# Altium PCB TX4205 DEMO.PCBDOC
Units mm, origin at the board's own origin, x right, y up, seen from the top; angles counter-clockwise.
Board outline 48.25 x 40.25 mm, 2 copper layers (Top Layer, Bottom Layer); 17 components, 8 nets, 42 pads, 163 vias.
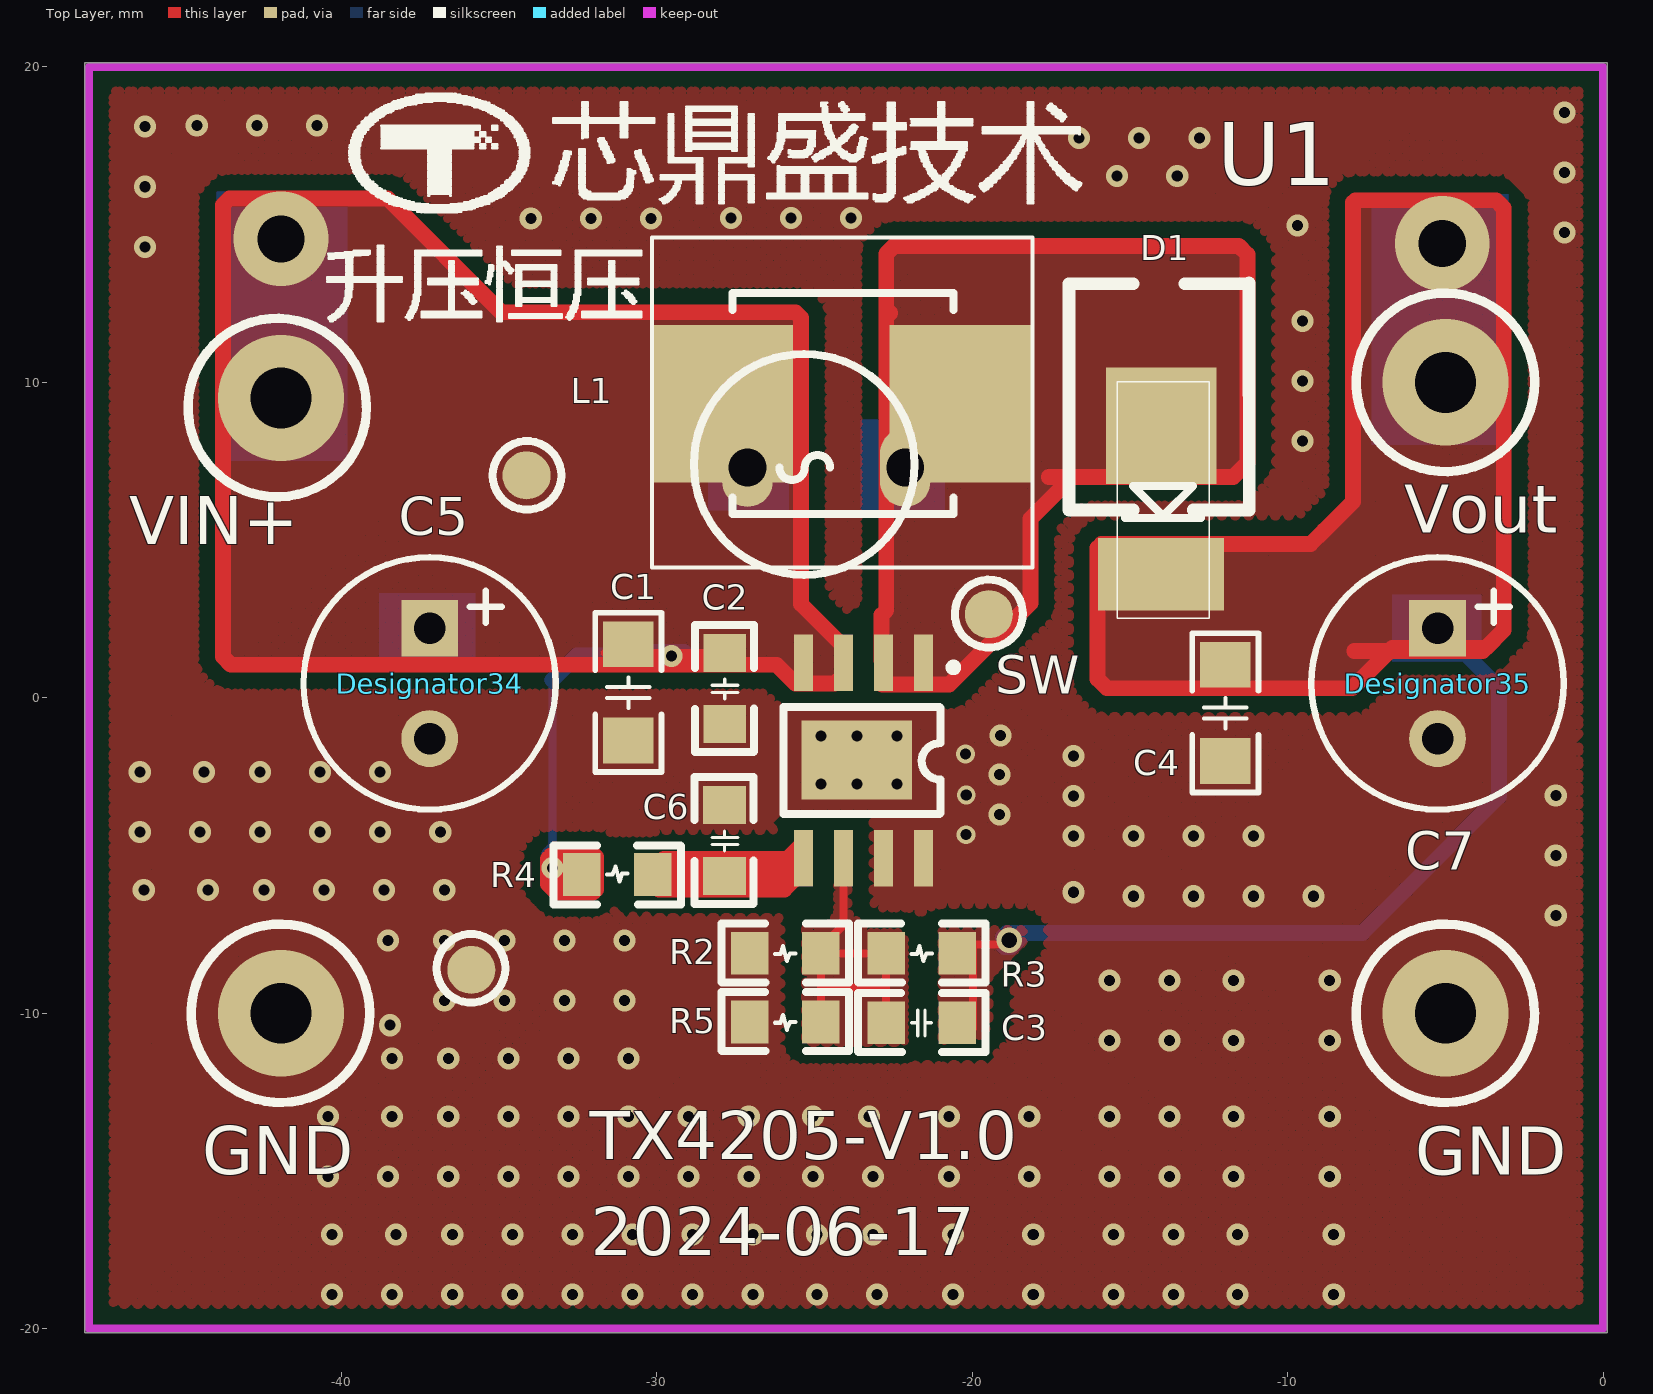
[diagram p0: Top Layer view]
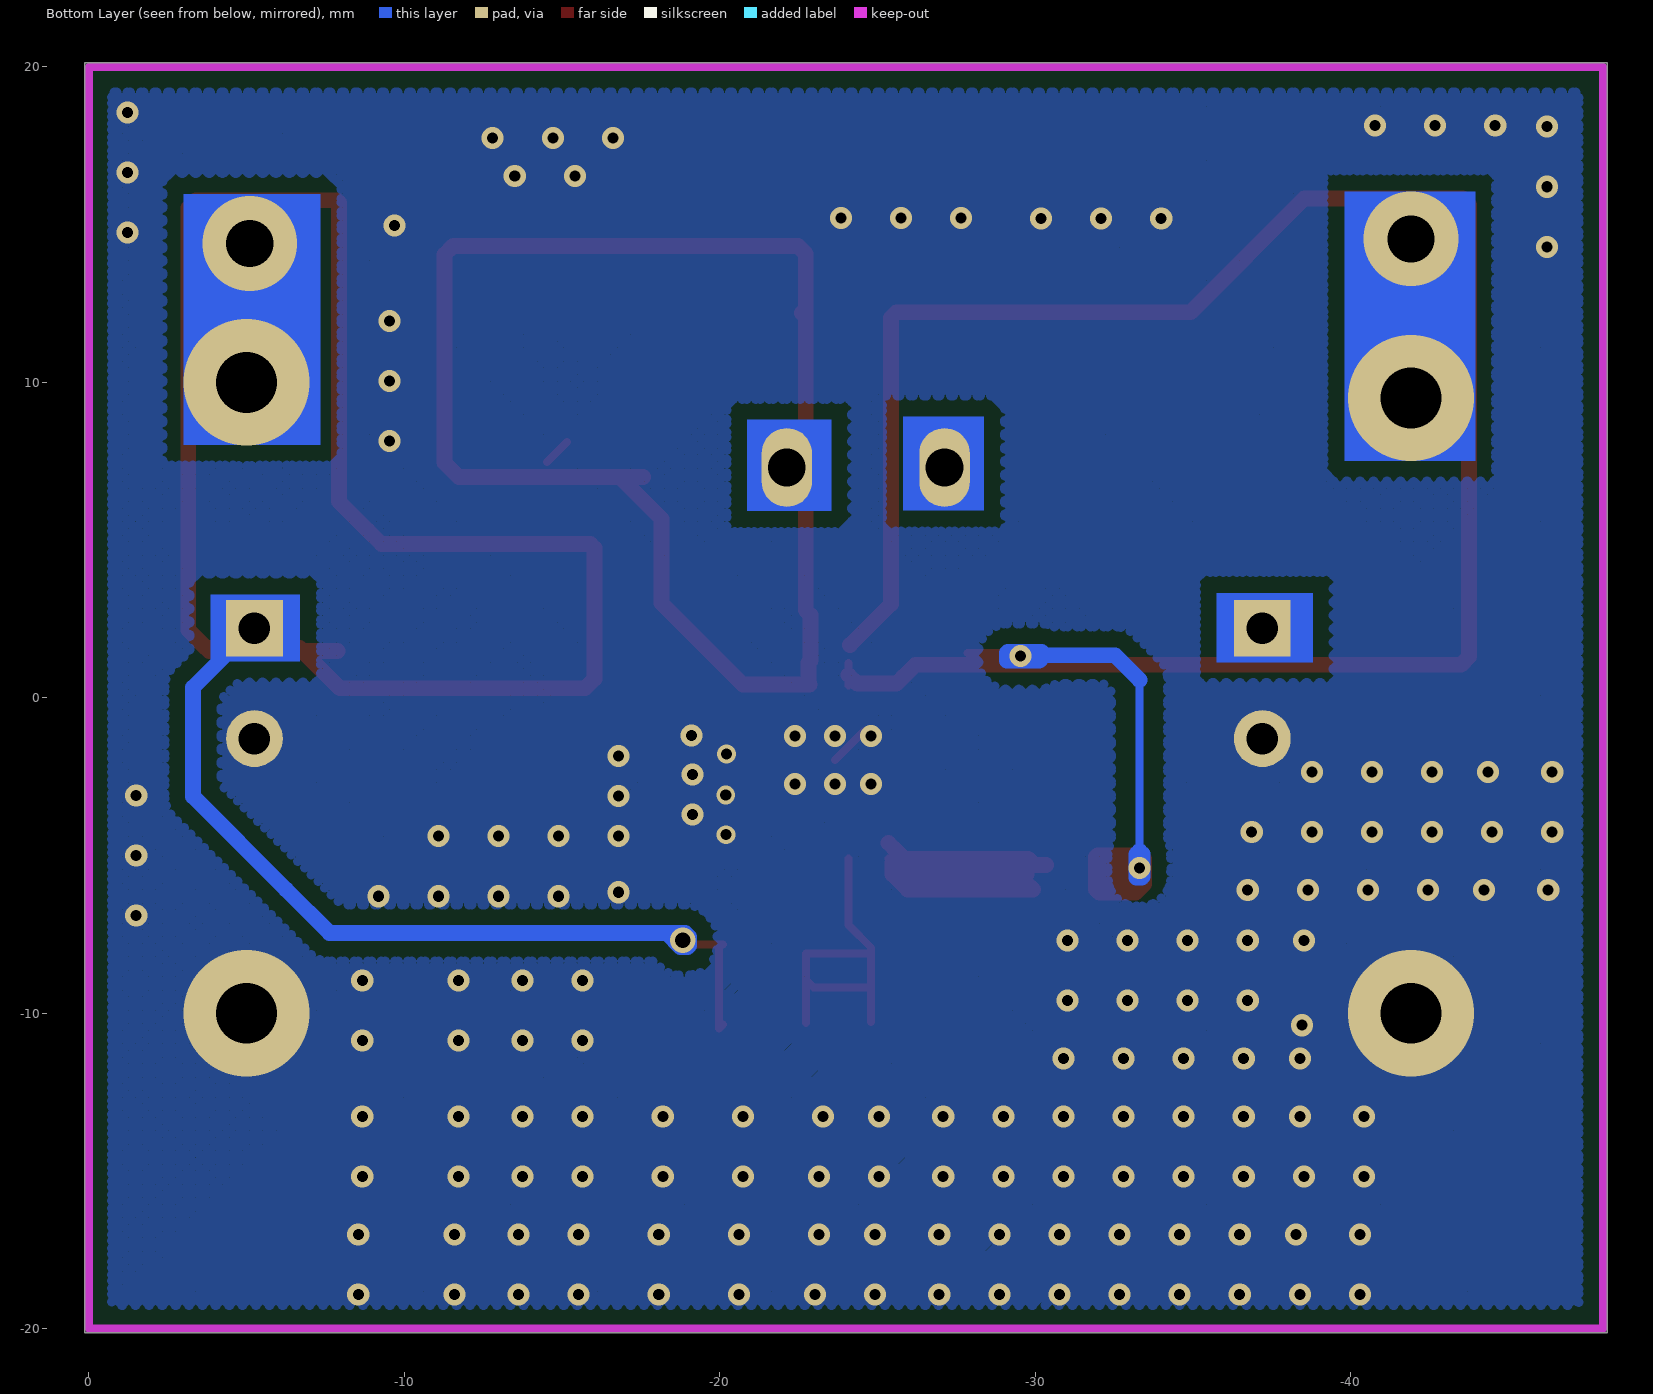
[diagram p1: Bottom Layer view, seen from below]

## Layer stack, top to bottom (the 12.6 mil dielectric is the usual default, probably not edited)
Top Layer: signal copper 0.0356
Dielectric: dielectric 0.32, FR-4, Dk 4.8
Bottom Layer: signal copper 0.0356

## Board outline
-48.127,-20.127 0.127,-20.127 0.127,20.127 -48.127,20.127

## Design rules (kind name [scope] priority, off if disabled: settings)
Clearance [All] p1: gap=0.5
PlaneConnect [All] p1: planeconnectstyle=Direct reliefexpansion=0.508 reliefentries=4 reliefconductorwidth=0.254 reliefairgap=0.254
PolygonConnect [All] p1: connectstyle=Direct reliefconductorwidth=0.254 reliefentries=4 polygonreliefangle="90 Angle"
RoutingLayers [All] p1: top layer_v5=FALSE bottom layer_v5=FALSE
RoutingVias [All] p1: holewidth=0.711 width=1.27 viastyle="Through Hole" minholewidth=0.711 minwidth=1.27 maxholewidth=0.711 maxwidth=1.27
SilkscreenOverComponentPads [All] p1: minsilkscreentomaskgap=0.254
SolderMaskExpansion [All] p1: expansion=0.102
TestPointUsage FabricationTestPointUsage [All] p1: valid=0 allowmultiple=FALSE
Testpoint FabricationTestpoint [All] p1: side=3 testpointundercomponent=TRUE minsize=1.016 maxsize=2.54 preferedsize=1.524 minholesize=0 maxholesize=1.016 preferedholesize=0.813 testpointgrid=0.025 style=297 order=0-112345678
Width [All] p1: maxlimit=1 minlimit=0.254 preferedwidth=0.5
21 further rules are at their usual default settings.

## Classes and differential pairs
component class XY9101A-B: C1 C2 C3 C4 C6 D1 L1 R2 R3 R4 U1

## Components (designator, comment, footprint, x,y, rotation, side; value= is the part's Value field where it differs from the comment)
C1 "Cap" C1206 -30.898,-1.353 r90 top
C2 "Cap" C0805 -27.844,-0.829 r90 top
C3 "Cap" C0805 -22.725,-10.3 r0 top
C4 "Cap" C1206 -11.973,-2.003 r90 top
C6 "Cap" C0805 -27.85,-5.65 r90 top
D1 "D Schottky" "Schottky Diode 20x10" -15.535,10.144 r270 top
Designator34 "Comment" C-RB-8 -37.35,-9.35 r270 top
Designator35 "Comment" C-RB-8 -5.4,-9.35 r270 top
L1 "Inductor" "inductor 10 x 10" -30.13,4.124 r0 top
R2 "Res1" R0805 -27.05,-8.1 r0 top
R3 "Res1" R0805 -22.725,-8.1 r0 top
R4 "Res1" R0805 -30.125,-5.6 r180 top
R5 "Res1" R0805 -27.05,-10.275 r0 top
U1 "TX4205" SOP8-Epad -26.193,2.092 r270 top
? "Comment" LOGO -36.875,17.775 r0 top
? "" LS7*7 -21.125,9.325 r0 top
? "" L2*3.5 -27.124,7.3 r0 top

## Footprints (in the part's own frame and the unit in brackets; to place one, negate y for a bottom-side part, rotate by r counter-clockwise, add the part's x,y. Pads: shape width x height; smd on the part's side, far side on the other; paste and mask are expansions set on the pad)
C0805 [mm]
  rect 1.2x1.35 smd: 1(0,0) 2(2.25,0)
  silkscreen extent -0.89,-0.93 3.14,0.95
C1206 [mm]
  rect 1.45x1.6 smd: 1(0,0) 2(3.05,0)
  silkscreen extent -1,-1.05 4.05,1.05
C-RB-8 [mm]
  rect 1.8x1.8 hole 1: 1(-11.557,0.152)
  round 1.8 hole 1: 2(-8.057,0.152)
  silkscreen extent -13.81,-3.85 -5.81,4.15
"inductor 10 x 10" [mm]
  rect 3x5 smd: 1(1.5,5.2) 2(10.5,5.2)
  silkscreen extent -0.03,0 12.04,10.46
L2*3.5 [mm]
  oval 1.6x2.5 hole 1.2: 1(0,0) 2(5,0)
  silkscreen extent -1.7,-3.4 5.3,3.6
LOGO [mm]
  silkscreen extent -2.88,-2.39 20.34,1.37
LS7*7 [mm]
  rect 3x5 smd: 1(0,0) 2(-6.05,0)
  silkscreen extent -6.48,-3.5 0.52,3.5
R0805 [mm]
  rect 1.2x1.35 smd: 1(0,0) 2(2.25,0)
  silkscreen extent -0.89,-0.93 3.14,0.95
"Schottky Diode 20x10" [mm]
  rect 3.7x3.5 smd: 1(1.524,1.524)
  rect 2.3x4 smd: 2(6.223,1.524)
  silkscreen extent 0.13,0.13 7.62,3.05
SOP8-Epad [mm]
  rect 1.8x0.6 smd: 1(0.981,4.653) 2(0.981,3.383) 3(0.981,2.113) 4(0.981,0.843) 5(7.181,0.843) 6(7.181,2.113) 7(7.181,3.383) 8(7.181,4.653)
  rect 2.5x3.5 smd: 1(4.064,2.54)
  silkscreen extent 1.01,0.21 5.78,5.72

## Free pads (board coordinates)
  round 1.524 smd: 1(-35.875,-8.625) 1(-34.125,7.05) 1(-19.47,2.651)

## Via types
v1: diameter 0.7, hole 0.35, Top Layer to Bottom Layer, 153 vias
v2: diameter 4, hole 1.93, Top Layer to Bottom Layer, 4 vias
v3: diameter 0.6, hole 0.35, Top Layer to Bottom Layer, 3 vias
v4: diameter 3, hole 1.5, Top Layer to Bottom Layer, 2 vias
v5: diameter 0.8, hole 0.5, Top Layer to Bottom Layer, 1 vias

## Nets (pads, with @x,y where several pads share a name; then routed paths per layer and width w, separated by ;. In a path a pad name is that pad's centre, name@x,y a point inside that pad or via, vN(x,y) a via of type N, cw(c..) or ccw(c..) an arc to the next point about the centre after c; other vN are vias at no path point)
COMP: 
COMPC: 
GND: C1.1 C2.1 C4.1 C6.2 Designator34.2 Designator35.2 pad.1@-35.875,-8.625 R2.1 R5.1 U1.1@-23.653,-1.972 U1.7 U1.8 | length 1.3
  Top Layer w0.254: U1.1@-24.574,-1.051 U1.1@-23.653,-1.972
  other v1: -40.29,-18.92 -38.385,-18.92 -36.48,-18.92 -34.575,-18.92 -32.67,-18.92 -30.765,-18.92 -28.86,-18.92 -26.955,-18.92 -24.923,-18.92 -23.018,-18.92 -20.605,-18.92 -18.065,-18.92 -15.525,-18.92 -13.62,-18.92 -11.588,-18.92 -8.54,-18.92 -40.29,-17.015 -38.258,-17.015 -36.48,-17.015 -34.575,-17.015 -32.67,-17.015 -30.765,-17.015 -28.86,-17.015 -26.955,-17.015 -24.923,-17.015 -23.145,-17.015 -20.605,-17.015 -18.065,-17.015 -15.525,-17.015 -13.62,-17.015 -11.588,-17.015 -8.54,-17.015 -40.417,-15.18 -38.512,-15.18 -36.607,-15.18 -34.702,-15.18 -32.797,-15.18 -30.892,-15.18 -28.987,-15.18 -27.082,-15.18 -25.05,-15.18 -23.145,-15.18 -20.732,-15.18 -18.192,-15.18 -15.652,-15.18 -13.747,-15.18 -11.715,-15.18 -8.667,-15.18 -40.417,-13.275 -38.385,-13.275 -36.607,-13.275 -34.702,-13.275 -32.797,-13.275 -30.892,-13.275 -28.987,-13.275 -27.082,-13.275 -25.05,-13.275 -23.272,-13.275 -20.732,-13.275 -18.192,-13.275 -15.652,-13.275 -13.747,-13.275 -11.715,-13.275 -8.667,-13.275 -38.385,-11.427 -36.607,-11.427 -34.702,-11.427 -32.797,-11.427 -30.892,-11.427 -15.652,-10.862 -13.747,-10.862 -11.715,-10.862 -8.667,-10.862 -38.448,-10.378 -36.734,-9.592 -34.829,-9.592 -32.924,-9.592 -31.019,-9.592 -15.652,-8.957 -13.747,-8.957 -11.715,-8.957 -8.667,-8.957 -38.512,-7.687 -36.734,-7.687 -34.829,-7.687 -32.924,-7.687 -31.019,-7.687 -14.89,-6.29 -12.985,-6.29 -11.08,-6.29 -9.175,-6.29 -16.795,-6.163 -46.259,-6.093 -44.227,-6.093 -42.449,-6.093 -40.544,-6.093 -38.639,-6.093 -36.734,-6.093 -16.795,-4.385 -14.89,-4.385 -12.985,-4.385 -11.08,-4.385 -46.386,-4.258 -44.481,-4.258 -42.576,-4.258 -40.671,-4.258 -38.766,-4.258 -36.861,-4.258 -19.14,-3.698 -16.795,-3.115 -24.796,-2.734 -23.653,-2.734 -22.383,-2.734 -19.139,-2.426 -46.386,-2.353 -44.354,-2.353 -42.576,-2.353 -40.671,-2.353 -38.766,-2.353 -16.795,-1.845 -24.796,-1.21 -23.653,-1.21 -22.383,-1.21 -19.104,-1.189 -9.693,14.973
  other v2: -41.908,-10 -5,-10
  other v3: -20.196,-4.34 -20.188,-3.075 -20.208,-1.782
NetC3_1: C3.1 R2.2 R3.1 R5.2 U1.6 | length 11.9
  Top Layer w0.254: R5.2 -24.8,-9.175 ; U1.6 -24.08,-7.205 -24.8,-7.925 R2.2 ; C3.1 -22.725,-8.925 ; -24.8,-9.175 R2.2 ; -24.8,-9.175 -22.975,-9.175 -22.725,-8.925 ; R2.2 R3.1 -22.725,-8.925
NetC3_2: C3.2 C4.2 D1.2 Designator35.1 R3.2 | length 90.9
  Top Layer w0.254: C3.2@-20.097,-10.354 -19.97,-10.481 R3.2@-19.97,-7.941 ; R3.2@-20.097,-7.814 -18.954,-7.814 v5(-18.827,-7.687)
  Top Layer w0.5: -7.89,1.485 -3.815,1.485 -3.675,1.625 ; -7.825,0.425 -7.175,1.075 -6.675,1.575 ; -6.675,1.575 -3.725,1.575 -3.15,2.15 -3.15,15.525 -3.25,15.625 -3.4,15.775 -3.9,15.775 -4.225,15.775 -7.85,15.775 -7.925,15.7 -7.925,6.225 -8.85,5.3 -9.275,4.875 -15.9,4.875 -16.025,4.75 -16.025,0.6 -15.725,0.3 -7.95,0.3 -6.675,1.575
  Bottom Layer w0.254: v5(-18.827,-7.687) v5@-18.597,-7.457
  Bottom Layer w0.5: v5(-18.827,-7.687) -18.597,-7.457 -7.632,-7.457 -6.25,-6.075 -3.3,-3.125 -3.3,0.325 Designator35.1@-5.45,2.475 ; -18.125,-7.457 -18.907,-7.457 -19.025,-7.575 -19.025,-7.85 -18.975,-7.9 -18.75,-7.9 -18.307,-7.457 -18.1,-7.457
  other v2: -5,10
  other v4: -5.1,14.4
NetC6_1: C6.1 R4.1 U1.5 | length 23.8
  Top Layer w0.254: R4.1@-29.908,-5.401 -27.85,-5.401 C6.1@-27.807,-5.401 ; C6.1@-27.742,-5.337 -25.598,-5.337 U1.5
  Top Layer w0.5: R4.1@-30.35,-5.3 -30.125,-5.3 -29.975,-5.3 -29.775,-5.1 -27.85,-5.1 -25.85,-5.1 -25.595,-4.845 U1.5@-25.35,-4.6 ; R4.1@-29.722,-5.597 -27.85,-5.597 U1.5@-25.472,-5.597 ; U1.5@-25.472,-5.211 U1.5@-25.472,-5.597 ; -25.875,-6 U1.5@-25.472,-5.597 ; -25.875,-6 -27.85,-6 -29.85,-6 -29.925,-6.075 -27.85,-6.075 -25.95,-6.075 -25.875,-6 ; -25.875,-6 U1.5@-25.472,-5.597
NetD1_1: ?.1@-21.125,9.325 ?.2@-22.124,7.3 D1.1 L1.2 pad.1@-19.47,2.651 U1.1@-21.54,1.111 U1.2 | length 49.9
  Top Layer w0.254: U1.2@-22.95,0.375 U1.2@-22.925,0.35 ; D1.1@-15.154,8.112 -14.837,7.794 D1.1@-14.519,7.477
  Top Layer w0.5: -22.6,12.2 -22.725,12.075 ; -17.575,7 -16.825,7 ; -22.725,12.075 -22.725,9.325 -22.725,7.3 -22.725,2.775 -22.875,2.625 -22.875,1.176 U1.2 -22.81,0.465 -22.85,0.425 -22.81,0.425 -21.54,0.425 -20.725,0.425 -18.985,2.165 -18.15,3 -18.15,5.675 -16.825,7 ; -22.725,12.075 -22.725,14.075 -22.475,14.325 -11.55,14.325 -11.275,14.05 -11.275,7.45 -11.725,7 -14.011,7 -16.825,7
VCC: ?.1@-27.124,7.3 ?.2@-27.175,9.325 C1.2 C2.2 Designator34.1 L1.1 R4.2 U1.3 U1.4 | length 96.3
  Top Layer w0.254: R4.2@-32.15,-5.401 R4.2@-32.375,-5.401 ; R4.2@-31.908,-5.401 -31.925,-5.401 R4.2@-32.375,-5.401 ; C1.2@-31.654,1.421 -30.898,1.421 -29.525,1.421 C2.2 ; U1.3@-24.08,0.395 -24.08,0.725 U1.3 ; R4.2@-32.375,-5.401 v1(-33.305,-5.401) R4.2@-32.375,-5.401
  Top Layer w0.5: U1.3@-24.125,1.675 -25.425,2.975 -25.425,12.05 -25.6,12.225 -34.925,12.225 -38.525,15.825 -41.908,15.825 -43.55,15.825 -43.75,15.625 -43.75,9.5 -43.75,1.3 -43.5,1.05 -30.898,1.05 -29.525,1.05 -27.844,1.05 -26.2,1.05 -25.806,0.655 -25.6,0.45 -25.35,0.45 -24.355,0.45 U1.3@-24.08,0.725 ; -33.45,-5.9 -33.175,-6.175 -32.375,-6.175 -32.025,-6.175 -31.925,-6.075 -31.925,-5.6 -31.925,-5.401 -31.925,-5.05 -31.975,-5 -32.375,-5 -33.305,-5 -33.35,-5 -33.45,-5.1 -33.45,-5.401 -33.45,-5.9
  Bottom Layer w0.254: v1(-33.305,-5.401) -33.305,-5.045 -33.305,-4.855 -33.305,0.568 -32.543,1.33 -30.276,1.326 v1(-29.525,1.325)
  Bottom Layer w0.5: -33.305,0.568 -32.543,1.33 -32.523,1.35 -30.3,1.35 ; -29.1,1.425 -29.1,1.325 -29.1,1.175 v1@-29.4,1.175 ; -33.4,-4.95 -33.4,-5.401 -33.4,-5.675 -33.375,-5.7 -33.305,-5.7 -33.2,-5.7 -33.2,-5.401 v1@-33.2,-5.15 ; -33.4,-4.95 -33.305,-4.855 -33.2,-4.96 v1@-33.2,-5.15 ; -33.4,-4.95 -33.305,-5.045 v1@-33.2,-5.15 ; -30.3,1.35 -30.2,1.45 -29.525,1.45 -29.125,1.45 -29.388,1.187 v1@-29.4,1.175 ; -30.3,1.35 -30.276,1.326 -30.125,1.175 -29.525,1.175 v1@-29.4,1.175
  other v2: -41.908,9.5
  other v4: -41.908,14.546
copper on no net:
  other v1: -1.501,-6.904 -1.501,-4.999 -1.501,-3.094 -9.533,8.137 -9.533,10.042 -9.533,11.947 -46.225,14.295 -1.227,14.746 -33.992,15.188 -32.087,15.188 -30.182,15.188 -27.645,15.206 -25.74,15.206 -23.835,15.206 -46.225,16.2 -15.405,16.542 -13.5,16.542 -1.227,16.651 -16.611,17.748 -14.706,17.748 -12.801,17.748 -46.225,18.105 -44.579,18.139 -42.674,18.139 -40.769,18.139 -1.227,18.556

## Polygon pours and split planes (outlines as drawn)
NetC3_1 on Top Layer "Top Layer-NetC3_1" (hatched 45Degree grid 0.3 track 0.3, pour order 1006): -24.08,-5.089 -24.08,-5.75 -24.255,-5.925 -24.255,-6.875 -24.675,-7.295 -25.275,-7.295 -25.275,-10.925 -22.15,-10.925 -22.15,-7.45 -23.3,-7.45 -23.775,-6.975 -23.95,-6.8 -23.95,-5.075
NetC3_2 on Top Layer "Top Layer-NetC3_2 1" (hatched 45Degree grid 0.3 track 0.3, pour order 1005): -20.75,-10.825 -19.9,-10.825 -19.475,-10.4 -19.475,-8.825 -19,-8.35 -18.4,-7.75 -18.4,-7.35 -20.95,-7.35 -20.95,-10.875
VCC on Top Layer "Top Layer-VCC 1" (hatched 45Degree grid 0.3 track 0.3, pour order 1004): -30.575,1.05 -26.2,1.05 -25.6,0.45 -24.355,0.45 -24.355,1.935 -25.395,2.975 -25.395,12.05 -34.1,12.05 -34.1,1.05
VCC on Top Layer "Top Layer-VCC" (hatched 45Degree grid 0.3 track 0.3, pour order 1003): -34.05,1.05 -43.5,1.05 -43.75,1.3 -43.75,15.625 -43.55,15.825 -38.525,15.825 -34.925,12.225 -34.1,12.225 -34.1,1.05
NetD1_1 on Top Layer "Top Layer-NetD1_1" (hatched 45Degree grid 0.3 track 0.3, pour order 1002): -20.725,0.425 -18.15,3 -18.15,5.675 -16.825,7 -11.7,7 -11.275,7.425 -11.275,14.05 -11.55,14.325 -22.475,14.325 -22.725,14.075 -22.725,0.425
NetC3_2 on Top Layer "Top Layer-NetC3_2" (hatched 45Degree grid 0.3 track 0.3, pour order 1001): -7.95,0.3 -15.725,0.3 -16.025,0.6 -16.025,4.75 -9.275,4.75 -7.925,6.1 -7.925,15.775 -3.4,15.775 -3.15,15.525 -3.15,2.15 -3.725,1.575 -6.675,1.575
GND on Top Layer "Top Layer-GND" (hatched 45Degree grid 0.3 track 0.3, pour order 1000): -47.6,19.55 -0.45,19.55 -0.45,-19.5 -47.5,-19.5 -47.5,19.575
GND on Bottom Layer "Bottom Layer-GND" (hatched 45Degree grid 0.3 track 0.3, pour order 1007): -47.25,19.2 -0.725,19.2 -0.725,-19.25 -47.225,-19.25 -47.225,19.175

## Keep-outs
Keep-Out Layer:
  lines w0.254: -48,-20 0,-20 0,0 0,20 -48,20 -48,-20

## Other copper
Top Layer:
  rectangle net VCC: -33.35,-6.075 -31.925,-5
Bottom Layer:
  rectangle net NetC3_2: -6.698,1.147 -3.848,3.277
  rectangle net VCC: -38.798,1.122 -35.748,3.326
  rectangle net VCC: -43.95,7.513 -39.8,11.5
  rectangle net VCC: -43.95,12.559 -39.8,16.05
  rectangle net VCC: -43.95,11.5 -39.8,12.559
  rectangle net NetC3_2: -7.342,8.019 -3,12.006
  rectangle net NetC3_2: -7.342,13.05 -3,15.975
  rectangle net NetC3_2: -7.342,12.006 -3,13.05
  rectangle net NetD1_1: -23.538,5.919 -20.868,8.817
  rectangle net VCC: -28.378,5.931 -25.8,8.919

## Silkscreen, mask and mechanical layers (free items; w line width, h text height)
Top Overlay:
  drawing of 625 lines, arcs and shapes, not listed
  text "Vout" at -6.3,5.225 h1.52
  text "C5" at -38.173,5.147 h1.2
  text "VIN+" at -46.725,4.875 h1.52
  text "SW" at -19.273,0.122 h1.2
  text "C7" at -6.273,-5.453 h1.2
  text "TX4205-V1.0" at -32.125,-14.625 h1.52
  text "GND" at -44.4,-15.1 h1.52
  text "GND" at -5.95,-15.125 h1.52
  text "2024-06-17" at -32.098,-17.665 h1.52
Top Solder:
  rectangle: -16.525,6.625 -11.6,12.775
